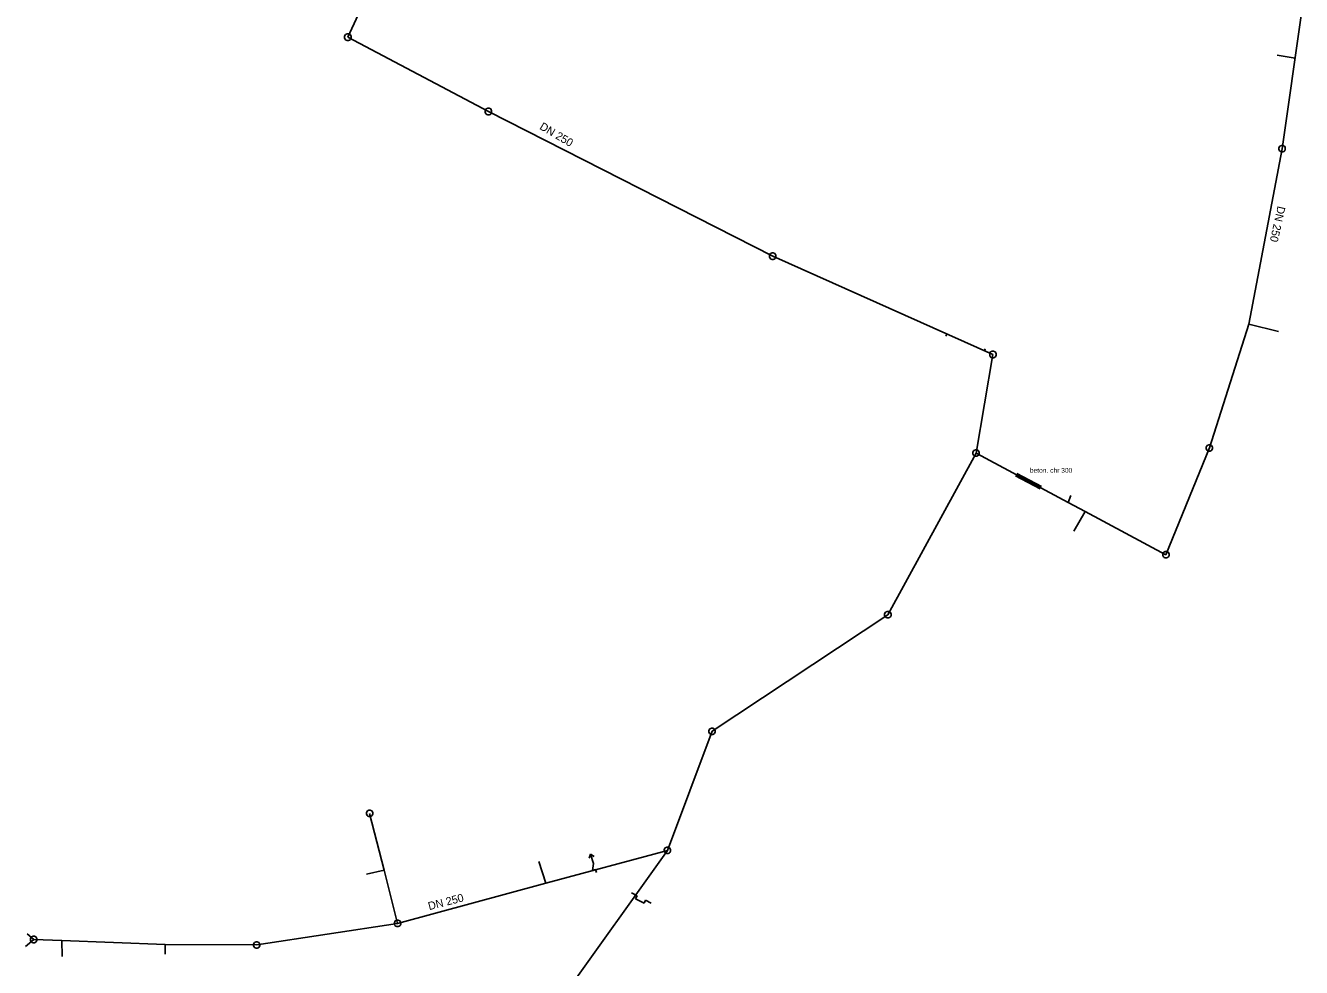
# Model space of a CAD drawing. Extents: x -717256 to -716843, y -1145423 to -1142840.
# Drawn here: x -717255.6 to -717056.2, y -1144052.4 to -1143905.3 of the extents above; entities that cross this region are included whole.
import ezdxf

# ---------------------------------------------------------------- set-up
doc = ezdxf.new("R2010")
doc.units = 0
for name, color, linetype in [('Vrstva 29', 7, 'Continuous'), ('Vrstva 30', 7, 'Continuous'), ('Vrstva 31', 7, 'Continuous'), ('Vrstva 9', 7, 'Continuous')]:
    doc.layers.add(name, color=color, linetype=linetype)

msp = doc.modelspace()

# ---------------------------------------------------------------- linework, layer by layer
at = {"layer": 'Vrstva 29'}
for p, q in [((-717097.068, -1143977.65), (-717100.889, -1143975.603)), ((-717100.7, -1143975.251), (-717096.879, -1143977.297))]:
    msp.add_line(p, q, dxfattribs=at)
at = {"layer": 'Vrstva 30'}
for p, q in [((-717205.219, -1143907.108), (-717184.759, -1143862.68)), ((-717059.26, -1143924.522), (-717056.237, -1143903.38)), ((-717205.569, -1143906.708), (-717205.319, -1143906.608)), ((-717205.319, -1143906.608), (-717205.119, -1143906.608)), ((-717205.119, -1143906.608), (-717204.869, -1143906.708)), ((-717205.719, -1143907.008), (-717205.669, -1143906.858)), ((-717205.719, -1143907.208), (-717205.719, -1143907.008)), ((-717205.619, -1143907.458), (-717205.719, -1143907.208)), ((-717205.669, -1143906.858), (-717205.569, -1143906.708)), ((-717205.469, -1143907.558), (-717205.619, -1143907.458)), ((-717205.319, -1143907.608), (-717205.469, -1143907.558)), ((-717205.119, -1143907.608), (-717205.319, -1143907.608)), ((-717205.219, -1143907.108), (-717183.255, -1143918.714)), ((-717204.969, -1143907.558), (-717205.119, -1143907.608)), ((-717204.819, -1143907.458), (-717204.969, -1143907.558)), ((-717204.869, -1143906.708), (-717204.769, -1143906.858)), ((-717204.719, -1143907.208), (-717204.819, -1143907.458)), ((-717204.769, -1143906.858), (-717204.719, -1143907.008)), ((-717204.719, -1143907.008), (-717204.719, -1143907.208)), ((-717183.755, -1143918.614), (-717183.705, -1143918.464)), ((-717183.705, -1143918.464), (-717183.605, -1143918.314)), ((-717183.605, -1143918.314), (-717183.355, -1143918.214)), ((-717183.355, -1143918.214), (-717183.155, -1143918.214)), ((-717183.155, -1143918.214), (-717182.905, -1143918.314)), ((-717182.905, -1143918.314), (-717182.805, -1143918.464)), ((-717182.805, -1143918.464), (-717182.755, -1143918.614)), ((-717183.755, -1143918.814), (-717183.755, -1143918.614)), ((-717183.655, -1143919.064), (-717183.755, -1143918.814)), ((-717183.505, -1143919.164), (-717183.655, -1143919.064)), ((-717183.355, -1143919.214), (-717183.505, -1143919.164)), ((-717183.155, -1143919.214), (-717183.355, -1143919.214)), ((-717183.255, -1143918.714), (-717138.85, -1143941.315)), ((-717183.005, -1143919.164), (-717183.155, -1143919.214)), ((-717182.855, -1143919.064), (-717183.005, -1143919.164)), ((-717182.755, -1143918.814), (-717182.855, -1143919.064)), ((-717182.755, -1143918.614), (-717182.755, -1143918.814)), ((-717064.479, -1143951.947), (-717059.26, -1143924.522)), ((-717059.76, -1143924.422), (-717059.71, -1143924.272)), ((-717059.76, -1143924.622), (-717059.76, -1143924.422)), ((-717059.71, -1143924.272), (-717059.61, -1143924.122)), ((-717059.61, -1143924.122), (-717059.36, -1143924.022)), ((-717059.36, -1143924.022), (-717059.16, -1143924.022)), ((-717059.16, -1143924.022), (-717058.91, -1143924.122)), ((-717058.91, -1143924.122), (-717058.81, -1143924.272)), ((-717058.81, -1143924.272), (-717058.76, -1143924.422)), ((-717058.76, -1143924.422), (-717058.76, -1143924.622)), ((-717059.66, -1143924.872), (-717059.76, -1143924.622)), ((-717059.51, -1143924.972), (-717059.66, -1143924.872)), ((-717059.36, -1143925.022), (-717059.51, -1143924.972)), ((-717059.16, -1143925.022), (-717059.36, -1143925.022)), ((-717059.01, -1143924.972), (-717059.16, -1143925.022)), ((-717058.86, -1143924.872), (-717059.01, -1143924.972)), ((-717058.76, -1143924.622), (-717058.86, -1143924.872)), ((-717139.35, -1143941.215), (-717139.3, -1143941.065)), ((-717139.35, -1143941.415), (-717139.35, -1143941.215)), ((-717139.25, -1143941.665), (-717139.35, -1143941.415)), ((-717139.3, -1143941.065), (-717139.2, -1143940.915)), ((-717139.1, -1143941.765), (-717139.25, -1143941.665)), ((-717139.2, -1143940.915), (-717138.95, -1143940.815)), ((-717138.95, -1143941.815), (-717139.1, -1143941.765)), ((-717138.95, -1143940.815), (-717138.75, -1143940.815)), ((-717138.75, -1143941.815), (-717138.95, -1143941.815)), ((-717138.85, -1143941.315), (-717104.449, -1143956.673)), ((-717138.75, -1143940.815), (-717138.5, -1143940.915)), ((-717138.6, -1143941.765), (-717138.75, -1143941.815)), ((-717138.45, -1143941.665), (-717138.6, -1143941.765)), ((-717138.5, -1143940.915), (-717138.4, -1143941.065)), ((-717138.35, -1143941.415), (-717138.45, -1143941.665)), ((-717138.4, -1143941.065), (-717138.35, -1143941.215)), ((-717138.35, -1143941.215), (-717138.35, -1143941.415)), ((-717070.628, -1143971.268), (-717064.479, -1143951.947)), ((-717104.949, -1143956.573), (-717104.899, -1143956.423)), ((-717104.899, -1143956.423), (-717104.799, -1143956.273)), ((-717104.799, -1143956.273), (-717104.549, -1143956.173)), ((-717104.549, -1143956.173), (-717104.349, -1143956.173)), ((-717104.349, -1143956.173), (-717104.099, -1143956.273)), ((-717104.099, -1143956.273), (-717103.999, -1143956.423)), ((-717103.999, -1143956.423), (-717103.949, -1143956.573)), ((-717104.449, -1143956.673), (-717107.076, -1143972.064)), ((-717104.949, -1143956.773), (-717104.949, -1143956.573)), ((-717104.849, -1143957.023), (-717104.949, -1143956.773)), ((-717104.699, -1143957.123), (-717104.849, -1143957.023)), ((-717104.549, -1143957.173), (-717104.699, -1143957.123)), ((-717104.349, -1143957.173), (-717104.549, -1143957.173)), ((-717104.199, -1143957.123), (-717104.349, -1143957.173)), ((-717104.049, -1143957.023), (-717104.199, -1143957.123)), ((-717103.949, -1143956.773), (-717104.049, -1143957.023)), ((-717103.949, -1143956.573), (-717103.949, -1143956.773)), ((-717107.076, -1143972.064), (-717120.861, -1143997.323)), ((-717107.576, -1143971.964), (-717107.526, -1143971.814)), ((-717107.576, -1143972.164), (-717107.576, -1143971.964)), ((-717107.476, -1143972.414), (-717107.576, -1143972.164)), ((-717107.526, -1143971.814), (-717107.426, -1143971.664)), ((-717107.426, -1143971.664), (-717107.176, -1143971.564)), ((-717107.176, -1143971.564), (-717106.976, -1143971.564)), ((-717107.076, -1143972.064), (-717092.695, -1143979.764)), ((-717106.976, -1143971.564), (-717106.726, -1143971.664)), ((-717106.726, -1143971.664), (-717106.626, -1143971.814)), ((-717106.576, -1143972.164), (-717106.676, -1143972.414)), ((-717106.626, -1143971.814), (-717106.576, -1143971.964)), ((-717106.576, -1143971.964), (-717106.576, -1143972.164)), ((-717077.417, -1143987.947), (-717070.628, -1143971.268)), ((-717071.128, -1143971.168), (-717071.078, -1143971.018)), ((-717071.128, -1143971.368), (-717071.128, -1143971.168)), ((-717071.028, -1143971.618), (-717071.128, -1143971.368)), ((-717071.078, -1143971.018), (-717070.978, -1143970.868)), ((-717070.878, -1143971.718), (-717071.028, -1143971.618)), ((-717070.978, -1143970.868), (-717070.728, -1143970.768)), ((-717070.728, -1143971.768), (-717070.878, -1143971.718)), ((-717070.728, -1143970.768), (-717070.528, -1143970.768)), ((-717070.528, -1143971.768), (-717070.728, -1143971.768)), ((-717070.528, -1143970.768), (-717070.278, -1143970.868)), ((-717070.378, -1143971.718), (-717070.528, -1143971.768)), ((-717070.228, -1143971.618), (-717070.378, -1143971.718)), ((-717070.278, -1143970.868), (-717070.178, -1143971.018)), ((-717070.128, -1143971.368), (-717070.228, -1143971.618)), ((-717070.178, -1143971.018), (-717070.128, -1143971.168)), ((-717070.128, -1143971.168), (-717070.128, -1143971.368)), ((-717107.326, -1143972.514), (-717107.476, -1143972.414)), ((-717107.176, -1143972.564), (-717107.326, -1143972.514)), ((-717106.976, -1143972.564), (-717107.176, -1143972.564)), ((-717106.826, -1143972.514), (-717106.976, -1143972.564)), ((-717106.676, -1143972.414), (-717106.826, -1143972.514)), ((-717092.695, -1143979.764), (-717090.024, -1143981.195)), ((-717090.024, -1143981.195), (-717077.417, -1143987.947)), ((-717077.917, -1143987.847), (-717077.867, -1143987.697)), ((-717077.917, -1143988.047), (-717077.917, -1143987.847)), ((-717077.817, -1143988.297), (-717077.917, -1143988.047)), ((-717077.867, -1143987.697), (-717077.767, -1143987.547)), ((-717077.667, -1143988.397), (-717077.817, -1143988.297)), ((-717077.767, -1143987.547), (-717077.517, -1143987.447)), ((-717077.517, -1143987.447), (-717077.317, -1143987.447)), ((-717077.317, -1143987.447), (-717077.067, -1143987.547)), ((-717077.017, -1143988.297), (-717077.167, -1143988.397)), ((-717077.067, -1143987.547), (-717076.967, -1143987.697)), ((-717076.917, -1143988.047), (-717077.017, -1143988.297)), ((-717076.967, -1143987.697), (-717076.917, -1143987.847)), ((-717076.917, -1143987.847), (-717076.917, -1143988.047)), ((-717077.517, -1143988.447), (-717077.667, -1143988.397)), ((-717077.317, -1143988.447), (-717077.517, -1143988.447)), ((-717077.167, -1143988.397), (-717077.317, -1143988.447)), ((-717120.861, -1143997.323), (-717148.325, -1144015.529)), ((-717121.361, -1143997.223), (-717121.311, -1143997.073)), ((-717121.361, -1143997.423), (-717121.361, -1143997.223)), ((-717121.261, -1143997.673), (-717121.361, -1143997.423)), ((-717121.311, -1143997.073), (-717121.211, -1143996.923)), ((-717121.111, -1143997.773), (-717121.261, -1143997.673)), ((-717121.211, -1143996.923), (-717120.961, -1143996.823)), ((-717120.961, -1143997.823), (-717121.111, -1143997.773)), ((-717120.961, -1143996.823), (-717120.761, -1143996.823)), ((-717120.761, -1143997.823), (-717120.961, -1143997.823)), ((-717120.761, -1143996.823), (-717120.511, -1143996.923)), ((-717120.611, -1143997.773), (-717120.761, -1143997.823)), ((-717120.461, -1143997.673), (-717120.611, -1143997.773)), ((-717120.511, -1143996.923), (-717120.411, -1143997.073)), ((-717120.361, -1143997.423), (-717120.461, -1143997.673)), ((-717120.411, -1143997.073), (-717120.361, -1143997.223)), ((-717120.361, -1143997.223), (-717120.361, -1143997.423)), ((-717148.325, -1144015.529), (-717155.294, -1144034.126)), ((-717148.825, -1144015.429), (-717148.775, -1144015.279)), ((-717148.825, -1144015.629), (-717148.825, -1144015.429)), ((-717148.725, -1144015.879), (-717148.825, -1144015.629)), ((-717148.775, -1144015.279), (-717148.675, -1144015.129)), ((-717148.575, -1144015.979), (-717148.725, -1144015.879)), ((-717148.675, -1144015.129), (-717148.425, -1144015.029)), ((-717148.425, -1144016.029), (-717148.575, -1144015.979)), ((-717148.425, -1144015.029), (-717148.225, -1144015.029)), ((-717148.225, -1144016.029), (-717148.425, -1144016.029)), ((-717148.225, -1144015.029), (-717147.975, -1144015.129)), ((-717148.075, -1144015.979), (-717148.225, -1144016.029)), ((-717147.925, -1144015.879), (-717148.075, -1144015.979)), ((-717147.975, -1144015.129), (-717147.875, -1144015.279)), ((-717147.825, -1144015.629), (-717147.925, -1144015.879)), ((-717147.875, -1144015.279), (-717147.825, -1144015.429)), ((-717147.825, -1144015.429), (-717147.825, -1144015.629)), ((-717202.324, -1144028.241), (-717202.274, -1144028.091)), ((-717202.274, -1144028.091), (-717202.174, -1144027.941)), ((-717202.174, -1144027.941), (-717201.924, -1144027.841)), ((-717201.924, -1144027.841), (-717201.724, -1144027.841)), ((-717201.724, -1144027.841), (-717201.474, -1144027.941)), ((-717201.474, -1144027.941), (-717201.374, -1144028.091)), ((-717201.374, -1144028.091), (-717201.324, -1144028.241)), ((-717202.324, -1144028.441), (-717202.324, -1144028.241)), ((-717202.224, -1144028.691), (-717202.324, -1144028.441)), ((-717202.074, -1144028.791), (-717202.224, -1144028.691)), ((-717201.924, -1144028.841), (-717202.074, -1144028.791)), ((-717201.724, -1144028.841), (-717201.924, -1144028.841)), ((-717201.824, -1144028.341), (-717199.566, -1144037.222)), ((-717201.574, -1144028.791), (-717201.724, -1144028.841)), ((-717201.424, -1144028.691), (-717201.574, -1144028.791)), ((-717201.324, -1144028.441), (-717201.424, -1144028.691)), ((-717201.324, -1144028.241), (-717201.324, -1144028.441)), ((-717182.99, -1144072.917), (-717155.294, -1144034.126)), ((-717174.283, -1144039.263), (-717155.294, -1144034.126)), ((-717155.794, -1144034.026), (-717155.744, -1144033.876)), ((-717155.794, -1144034.226), (-717155.794, -1144034.026)), ((-717155.744, -1144033.876), (-717155.644, -1144033.726)), ((-717155.644, -1144033.726), (-717155.394, -1144033.626)), ((-717155.394, -1144033.626), (-717155.194, -1144033.626)), ((-717155.194, -1144033.626), (-717154.944, -1144033.726)), ((-717154.944, -1144033.726), (-717154.844, -1144033.876)), ((-717154.844, -1144033.876), (-717154.794, -1144034.026)), ((-717154.794, -1144034.026), (-717154.794, -1144034.226)), ((-717155.694, -1144034.476), (-717155.794, -1144034.226)), ((-717155.544, -1144034.576), (-717155.694, -1144034.476)), ((-717155.394, -1144034.626), (-717155.544, -1144034.576)), ((-717155.194, -1144034.626), (-717155.394, -1144034.626)), ((-717155.044, -1144034.576), (-717155.194, -1144034.626)), ((-717154.894, -1144034.476), (-717155.044, -1144034.576)), ((-717154.794, -1144034.226), (-717154.894, -1144034.476)), ((-717199.566, -1144037.222), (-717197.455, -1144045.533)), ((-717197.455, -1144045.533), (-717174.283, -1144039.263)), ((-717219.462, -1144048.905), (-717197.455, -1144045.533)), ((-717197.955, -1144045.433), (-717197.905, -1144045.283)), ((-717197.955, -1144045.633), (-717197.955, -1144045.433)), ((-717197.855, -1144045.883), (-717197.955, -1144045.633)), ((-717197.905, -1144045.283), (-717197.805, -1144045.133)), ((-717197.705, -1144045.983), (-717197.855, -1144045.883)), ((-717197.805, -1144045.133), (-717197.555, -1144045.033)), ((-717197.555, -1144046.033), (-717197.705, -1144045.983)), ((-717197.555, -1144045.033), (-717197.355, -1144045.033)), ((-717197.355, -1144046.033), (-717197.555, -1144046.033)), ((-717197.355, -1144045.033), (-717197.105, -1144045.133)), ((-717197.205, -1144045.983), (-717197.355, -1144046.033)), ((-717197.055, -1144045.883), (-717197.205, -1144045.983)), ((-717197.105, -1144045.133), (-717197.005, -1144045.283)), ((-717196.955, -1144045.633), (-717197.055, -1144045.883)), ((-717197.005, -1144045.283), (-717196.955, -1144045.433)), ((-717196.955, -1144045.433), (-717196.955, -1144045.633)), ((-717254.797, -1144047.948), (-717254.747, -1144047.798)), ((-717254.797, -1144048.148), (-717254.797, -1144047.948)), ((-717254.747, -1144047.798), (-717254.647, -1144047.648)), ((-717254.647, -1144047.648), (-717254.397, -1144047.548)), ((-717254.397, -1144047.548), (-717254.197, -1144047.548)), ((-717254.297, -1144048.048), (-717249.916, -1144048.209)), ((-717254.197, -1144047.548), (-717253.947, -1144047.648)), ((-717253.947, -1144047.648), (-717253.847, -1144047.798)), ((-717253.847, -1144047.798), (-717253.797, -1144047.948)), ((-717253.797, -1144047.948), (-717253.797, -1144048.148)), ((-717254.697, -1144048.398), (-717254.797, -1144048.148)), ((-717254.547, -1144048.498), (-717254.697, -1144048.398)), ((-717254.397, -1144048.548), (-717254.547, -1144048.498)), ((-717254.197, -1144048.548), (-717254.397, -1144048.548)), ((-717254.047, -1144048.498), (-717254.197, -1144048.548)), ((-717253.897, -1144048.398), (-717254.047, -1144048.498)), ((-717253.797, -1144048.148), (-717253.897, -1144048.398)), ((-717249.916, -1144048.209), (-717233.736, -1144048.805)), ((-717233.736, -1144048.805), (-717219.462, -1144048.905)), ((-717219.962, -1144048.805), (-717219.912, -1144048.655)), ((-717219.962, -1144049.005), (-717219.962, -1144048.805)), ((-717219.862, -1144049.255), (-717219.962, -1144049.005)), ((-717219.912, -1144048.655), (-717219.812, -1144048.505)), ((-717219.712, -1144049.355), (-717219.862, -1144049.255)), ((-717219.812, -1144048.505), (-717219.562, -1144048.405)), ((-717219.562, -1144049.405), (-717219.712, -1144049.355)), ((-717219.562, -1144048.405), (-717219.362, -1144048.405)), ((-717219.362, -1144049.405), (-717219.562, -1144049.405)), ((-717219.362, -1144048.405), (-717219.112, -1144048.505)), ((-717219.212, -1144049.355), (-717219.362, -1144049.405)), ((-717219.062, -1144049.255), (-717219.212, -1144049.355)), ((-717219.112, -1144048.505), (-717219.012, -1144048.655)), ((-717218.962, -1144049.005), (-717219.062, -1144049.255)), ((-717219.012, -1144048.655), (-717218.962, -1144048.805)), ((-717218.962, -1144048.805), (-717218.962, -1144049.005))]:
    msp.add_line(p, q, dxfattribs=at)
at = {"layer": 'Vrstva 31'}
for p, q in [((-717057.239, -1143910.39), (-717060.057, -1143909.911)), ((-717064.479, -1143951.947), (-717059.845, -1143953.069)), ((-717111.775, -1143953.814), (-717111.621, -1143953.47)), ((-717105.64, -1143955.794), (-717105.769, -1143956.083)), ((-717092.275, -1143978.686), (-717092.695, -1143979.764)), ((-717091.79, -1143984.287), (-717090.024, -1143981.195)), ((-717175.373, -1144035.864), (-717174.283, -1144039.263)), ((-717199.566, -1144037.222), (-717202.296, -1144037.858)), ((-717254.297, -1144048.048), (-717255.577, -1144049.162)), ((-717254.297, -1144048.048), (-717255.333, -1144047.142)), ((-717249.839, -1144050.678), (-717249.916, -1144048.209)), ((-717233.757, -1144050.322), (-717233.736, -1144048.805))]:
    msp.add_line(p, q, dxfattribs=at)
at = {"layer": 'Vrstva 9'}
for p, q in [((-717167.515, -1144035.344), (-717167.289, -1144034.745)), ((-717166.826, -1144036.172), (-717167.289, -1144034.745)), ((-717167.289, -1144034.745), (-717166.754, -1144035.097)), ((-717166.992, -1144037.277), (-717166.826, -1144036.172)), ((-717166.516, -1144037.123), (-717166.992, -1144037.277)), ((-717166.362, -1144037.598), (-717166.516, -1144037.123)), ((-717160.931, -1144040.777), (-717160.04, -1144041.231)), ((-717160.04, -1144041.231), (-717160.267, -1144041.677)), ((-717160.267, -1144041.677), (-717158.93, -1144042.358)), ((-717158.93, -1144042.358), (-717158.703, -1144041.912)), ((-717158.703, -1144041.912), (-717157.812, -1144042.366))]:
    msp.add_line(p, q, dxfattribs=at)

# ---------------------------------------------------------------- texts
at = {"layer": 'Vrstva 30'}
for rotation, p in [(329.4, (-717175.373, -1143921.399)), (257.4, (-717059.953, -1143933.412)), (14.4, (-717192.508, -1144043.468))]:
    msp.add_text('DN 250', height=1.25, rotation=rotation, dxfattribs=at).set_placement(p)
msp.add_text('beton. chr 300', height=0.74999, dxfattribs=at).set_placement((-717098.667, -1143975.145))

doc.saveas('drawing.dxf')
